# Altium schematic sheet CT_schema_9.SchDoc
size 278 x 170 mm
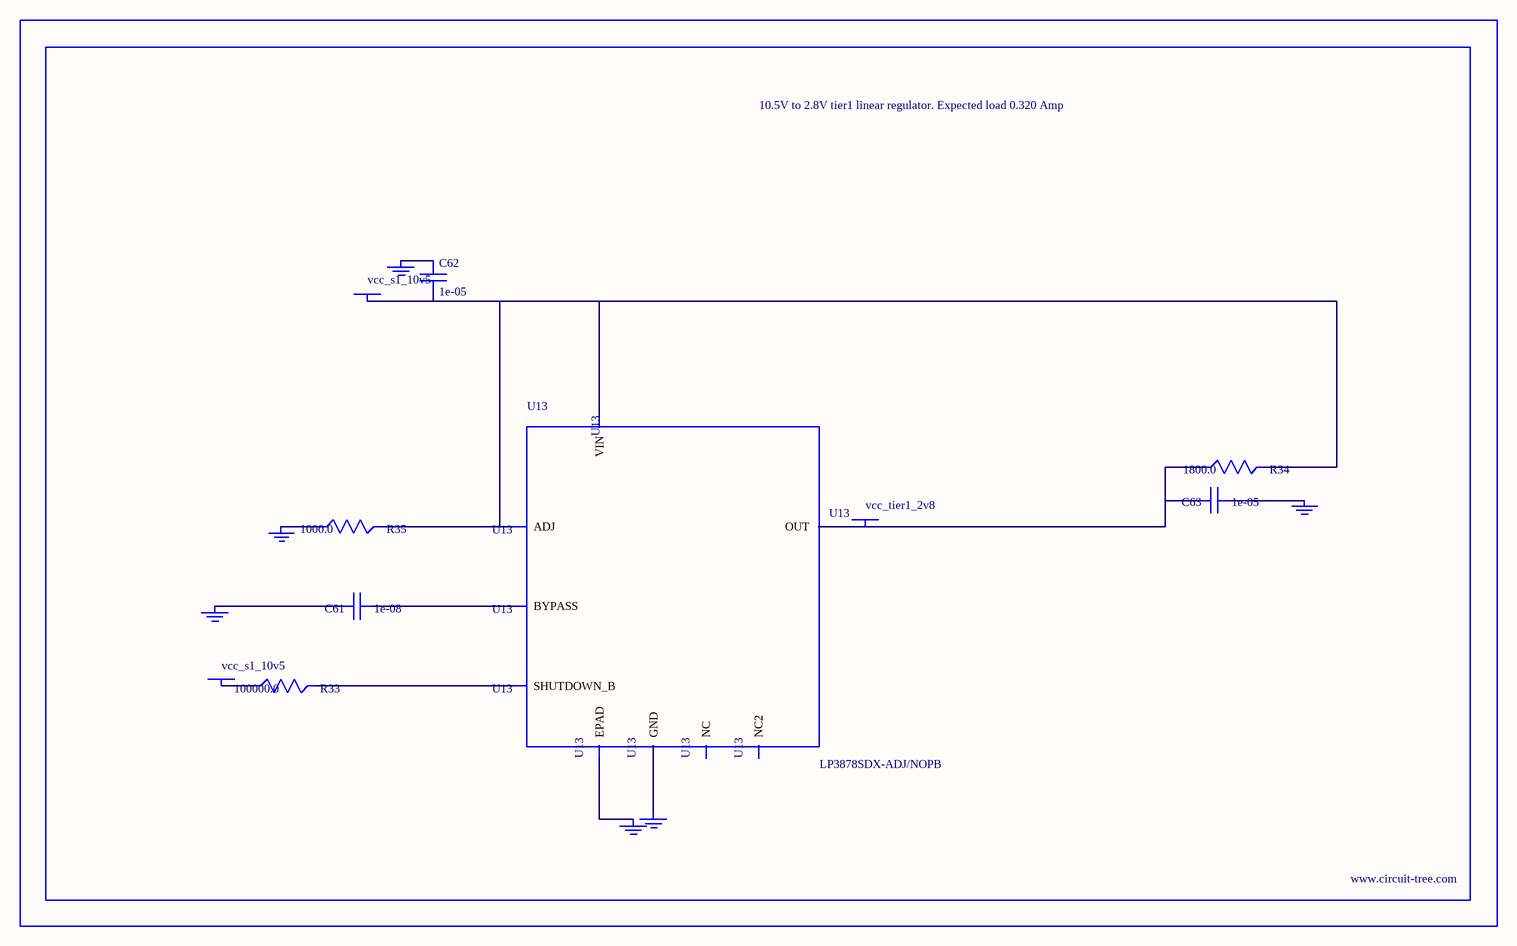
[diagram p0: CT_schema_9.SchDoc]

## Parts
BORDER8  (no value)
C61  1e-08  [C0402]
C62  1e-05  [C1206]
C63  1e-05  [C1210]
GND_INSTANCE_8_0  (no value)
GND_INSTANCE_8_1  (no value)
GND_INSTANCE_8_2  (no value)
GND_INSTANCE_8_3  (no value)
GND_INSTANCE_8_4  (no value)
GND_INSTANCE_8_5  (no value)
POWER_INSTANCE_8_0  vcc_s1_10v5
POWER_INSTANCE_8_1  vcc_s1_10v5
POWER_INSTANCE_8_2  vcc_tier1_2v8
R33  100000.0  [R0603]
R34  1800.0  [R0603]
R35  1000.0  [R0603]
U13  LP3878SDX-ADJ/NOPB  [WSON-8]

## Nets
NetC61_1: C61.1 U13.1(BYPASS)
NetC61_2: C61.2 GND_INSTANCE_8_0.0(GND)
NetC62_1: C62.1 GND_INSTANCE_8_1.0(GND)
NetC62_2: C62.2 POWER_INSTANCE_8_0.0(PWR) R34.2 R35.2 U13.4(VIN) U13.6(ADJ)
NetC63_1: C63.1 GND_INSTANCE_8_2.0(GND)
NetC63_2: C63.2 POWER_INSTANCE_8_2.0(PWR) R34.1 U13.5(OUT)
NetGND_INSTANCE_8_3_0: GND_INSTANCE_8_3.0(GND) R35.1
NetGND_INSTANCE_8_4_0: GND_INSTANCE_8_4.0(GND) U13.PAD(EPAD)
NetGND_INSTANCE_8_5_0: GND_INSTANCE_8_5.0(GND) U13.3(GND)
NetPOWER_INSTANCE_8_1_0: POWER_INSTANCE_8_1.0(PWR) R33.1
NetR33_2: R33.2 U13.8(SHUTDOWN_B)

Not connected (* = marked no-connect by the designer): U13 2(NC) 7(NC2)

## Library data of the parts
BORDER8 = BORDER_PAGE8
C61 = C0402C103K3RAC
C62 = C1206C106K3RACTU
C63 = GRM32DR61E106MA12L
GND_INSTANCE_8_0-GND_INSTANCE_8_5 = GND
POWER_INSTANCE_8_0-POWER_INSTANCE_8_2 = PWR
R33 = RC0603JR-07100KL
R34 = RC0603JR-071K8L
R35 = RC0603JR-071KL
